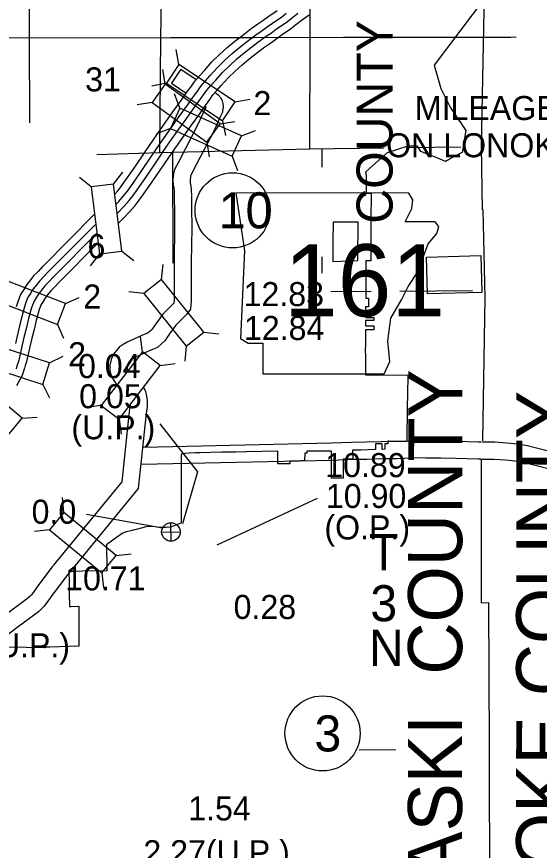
# Model space of a CAD drawing. Extents: x 1127717 to 1741049, y 2026793 to 2244711.
# Drawn here: x 1243581 to 1248173, y 2140586 to 2147909 of the extents above; entities that cross this region are included whole.
import ezdxf

# ---------------------------------------------------------------- set-up
doc = ezdxf.new("R2010")
doc.units = 0
for name, color, linetype in [('10', 7, 'Continuous'), ('15', 7, 'Continuous'), ('2', 7, 'Continuous'), ('20', 7, 'Continuous'), ('21', 7, 'Continuous'), ('25', 7, 'Continuous'), ('27', 7, 'Continuous'), ('30', 7, 'Continuous'), ('4', 7, 'Continuous'), ('5', 7, 'Continuous'), ('58', 7, 'Continuous'), ('6', 7, 'Continuous'), ('Level 30', 7, 'Continuous')]:
    doc.layers.add(name, color=color, linetype=linetype)

msp = doc.modelspace()

# ---------------------------------------------------------------- linework, layer by layer
at = {"layer": '10'}
for points in [[(1245024.4, 2147449.2), (1244939.9, 2147325.2), (1245069.5, 2147236.7)], [(1245024.4, 2147449.2), (1245158.6, 2147357.8)], [(1245324.8, 2147243.9), (1245333.9, 2147236.8), (1245350.9, 2147223.7), (1245374.5, 2147194.8), (1245385.9, 2147169.6), (1245391.2, 2147147.8), (1245394.7, 2147120.3), (1245391.6, 2147092.9), (1245390.1, 2147083.9), (1245387.8, 2147069.8), (1245378.9, 2147047.5), (1245363.6, 2147017.2), (1245338.1, 2146962.1), (1245311.8, 2146904.5), (1245132.7, 2146558.7)], [(1245234.6, 2147123.5), (1245241.4, 2147118.2), (1245242.4, 2147117.4), (1245242, 2147113.4), (1245241.5, 2147110.4), (1245241.1, 2147109.4), (1245227.6, 2147082.9), (1245200.8, 2147024.9), (1245175.4, 2146969.2), (1244998.8, 2146626.3)], [(1244998.8, 2146626.3), (1244974.7, 2146578.6), (1244968.4, 2146563.9), (1244964.3, 2146551.3), (1244960, 2146533.3), (1244954.2, 2146476.3), (1244953.8, 2146456.6), (1244954.9, 2146439.8), (1244956.7, 2146426.6), (1244960.5, 2146412.4), (1244962, 2146405), (1244964.1, 2146377.2), (1244965.9, 2146332.6)], [(1245132.7, 2146558.7), (1245110.7, 2146515.1), (1245108.9, 2146510.8), (1245108.7, 2146510.3), (1245108.2, 2146508.2), (1245104.1, 2146467), (1245103.9, 2146459.7), (1245104.1, 2146455.9), (1245106.5, 2146446.7), (1245110.8, 2146426.1), (1245113.9, 2146385.8), (1245115.7, 2146338.5)], [(1244965.9, 2146332.6), (1244966.5, 2146179), (1244968.4, 2146102.4), (1244968.6, 2146020.3), (1244967.6, 2145940.7), (1244965.7, 2145877.6), (1244964.7, 2145778.9), (1244963.9, 2145695.1), (1244964.4, 2145606.7), (1244964.2, 2145517.3), (1244964.1, 2145468), (1244964.3, 2145419.3), (1244962.4, 2145393.3), (1244961.7, 2145392.5), (1244866.1, 2145296.7)], [(1245115.9, 2146333.3), (1245116.5, 2146181.1), (1245118.4, 2146104.5), (1245118.6, 2146019.6), (1245117.6, 2145937.5), (1245115.7, 2145874.5), (1245114.7, 2145777.4), (1245113.9, 2145694.8), (1245114.4, 2145607), (1245114.2, 2145517), (1245114.1, 2145468), (1245114.3, 2145414.1), (1245108.8, 2145339.5), (1245076, 2145294.6), (1244980.1, 2145198.6)], [(1244265.7, 2146173.8), (1243809.8, 2145715.8)], [(1244276.4, 2146087.1), (1243858.5, 2145667.3)], [(1244286.2, 2146008.3), (1243902.8, 2145623.2)], [(1244296.9, 2145921.6), (1243951.5, 2145574.7)], [(1244866.1, 2145296.7), (1244802.1, 2145210.1), (1244769, 2145160.9), (1244755.9, 2145148.9), (1244736.7, 2145132.3), (1244715.7, 2145123.2), (1244680.2, 2145108.9), (1244550.1, 2145050.5), (1244515, 2145030.5), (1244482.4, 2145006.2), (1244456.6, 2144976.6), (1244429.3, 2144940.4), (1244411.4, 2144898.4), (1244400.1, 2144848.9), (1244400, 2144798.5), (1244411.7, 2144756.9), (1244428.4, 2144721), (1244452.7, 2144686.6), (1244459.6, 2144679.1)], [(1244980.1, 2145198.6), (1244924.7, 2145123.6), (1244883.4, 2145062.3), (1244855.7, 2145037), (1244817.5, 2145003.8), (1244773.4, 2144984.8), (1244739, 2144970.9), (1244618, 2144916.5), (1244597.2, 2144904.7), (1244584.9, 2144895.6), (1244573.1, 2144882), (1244560.1, 2144864.8), (1244554.7, 2144852), (1244550.1, 2144831.9), (1244550.1, 2144819.1), (1244552.9, 2144809), (1244557.3, 2144799.6)], [(1244693.8, 2144655.6), (1244697.7, 2144649.4), (1244712.4, 2144617.5), (1244722.2, 2144576.2), (1244725.9, 2144537.2), (1244726.9, 2144484.7), (1244721.9, 2144442.3), (1244716.4, 2144396.5), (1244649.2, 2143763.3), (1244016.9, 2142992.7)], [(1244576.5, 2144506.7), (1244576.8, 2144492.1), (1244573, 2144460.1), (1244567.3, 2144413.4), (1244504.7, 2143823.8), (1243900.9, 2143087.8)], [(1247664.5, 2144170.7), (1247637.9, 2144170.7), (1247443.6, 2144176.8), (1247311.4, 2144180.4), (1247180.9, 2144181.4), (1247141.5, 2144183.3), (1247047.7, 2144180.5), (1246920, 2144176.1), (1246784.7, 2144173.5), (1246653.7, 2144170.1), (1246521.6, 2144168.1), (1246345.9, 2144161.2), (1244694.8, 2144124.4)], [(1247672.2, 2144173), (1247781.7, 2144173.1), (1247888.2, 2144166.6), (1247950.3, 2144158.9), (1247973, 2144157.1), (1248019.2, 2144151.8), (1248065.5, 2144141.6), (1248438.7, 2144048.5)], [(1247663.1, 2144020.7), (1247635.4, 2144020.7), (1247439.2, 2144026.9), (1247308.7, 2144030.4), (1247176.7, 2144031.4), (1247140.1, 2144033.2), (1247052.5, 2144030.6), (1246924, 2144026.2), (1246788.1, 2144023.6), (1246656.9, 2144020.1), (1246525.7, 2144018.1), (1246350.5, 2144011.3), (1244673.1, 2143973.8)], [(1247671.4, 2144023), (1247777.1, 2144023.1), (1247874.4, 2144017.1), (1247935.2, 2144009.7), (1247958.5, 2144007.8), (1247994.3, 2144003.7), (1248031.1, 2143995.6), (1248402.3, 2143903)], [(1243898.9, 2143085.3), (1243769, 2142912), (1243734.4, 2142862.7), (1243709.9, 2142830.5), (1243698.6, 2142819.4), (1243674.7, 2142797.3), (1243491.4, 2142660.2), (1243211.8, 2142447.8), (1242963, 2142262.3), (1242790.6, 2142134.3), (1242584.6, 2141983.8), (1242522, 2141937.1), (1242493.2, 2141917.6), (1242476.6, 2141902.6), (1242450.7, 2141877.1), (1242424.4, 2141844.8), (1242306.6, 2141708.8), (1242245, 2141634.7), (1242230.2, 2141613.9)], [(1244018.9, 2142995.3), (1243890.4, 2142823.9), (1243855.5, 2142774.2), (1243822.8, 2142731.1), (1243802.2, 2142710.9), (1243771, 2142681.9), (1243581.7, 2142540.4), (1243302, 2142328), (1243052.6, 2142142), (1242879.6, 2142013.5), (1242673.7, 2141863.1), (1242608.9, 2141814.8), (1242585.9, 2141799.2), (1242579.4, 2141793.3), (1242561.8, 2141776), (1242539.3, 2141748.4), (1242421, 2141611.8), (1242363.9, 2141543.1), (1242339.2, 2141508.4), (1242308.1, 2141461.2), (1242275.8, 2141417), (1242253.4, 2141381.2), (1242227.4, 2141356.2)]]:
    msp.add_lwpolyline(points, dxfattribs=at)
at = {"layer": '15'}
for points in [[(1244443.3, 2146351), (1244468.1, 2146379), (1244498.4, 2146416.7), (1244526.1, 2146455.9), (1244613, 2146579.5), (1244708.9, 2146720.8), (1244784.4, 2146832.9), (1244890.6, 2146984.9), (1244953.7, 2147073.3), (1245025.7, 2147172.7), (1245077.2, 2147247), (1245115.6, 2147297.8), (1245146.2, 2147343.6), (1245189.3, 2147392.7), (1245230.1, 2147437.6), (1245295.8, 2147511.1), (1245358.8, 2147573.9), (1245430.3, 2147638.5), (1245498.5, 2147693.9), (1245566.5, 2147746.9), (1245642, 2147804.9), (1245699.3, 2147844.8), (1245742.5, 2147874.5), (1245788.7, 2147908.7), (1245869.4, 2147964.4)], [(1244454.4, 2146261), (1244477.5, 2146285.9), (1244520.7, 2146334.7), (1244553.3, 2146375.3), (1244582.3, 2146416.3), (1244669.5, 2146540.4), (1244765.9, 2146682.3), (1244841.1, 2146794), (1244946.7, 2146945.3), (1245009.5, 2147033.2), (1245081.8, 2147133), (1245132.9, 2147206.6), (1245171.7, 2147257.9), (1245200.9, 2147301.7), (1245240.5, 2147346.9), (1245281.2, 2147391.6), (1245345.7, 2147463.8), (1245406.2, 2147524), (1245475, 2147586.3), (1245541.3, 2147640.2), (1245608.6, 2147692.6), (1245682.6, 2147749.4), (1245738.4, 2147788.2), (1245782.4, 2147818.6), (1245828.7, 2147852.7), (1245910.1, 2147909), (1245949.8, 2147939.9)], [(1244464.4, 2146180), (1244523.8, 2146243.9), (1244568.5, 2146294.4), (1244603.2, 2146337.6), (1244633.4, 2146380.2), (1244721, 2146504.9), (1244817.6, 2146647.3), (1244892.7, 2146758.7), (1244997.8, 2146909.2), (1245060.3, 2146996.7), (1245132.8, 2147096.8), (1245183.6, 2147170), (1245222.6, 2147221.7), (1245250.6, 2147263.6), (1245287.2, 2147305.3), (1245327.6, 2147349.7), (1245391.1, 2147420.8), (1245449.2, 2147478.7), (1245515.7, 2147538.8), (1245580.2, 2147591.3), (1245646.8, 2147643.1), (1245719.4, 2147698.9), (1245774, 2147736.8), (1245818.7, 2147767.7), (1245865, 2147801.8), (1245947.2, 2147858.6), (1245988.2, 2147890.6), (1246051.3, 2147939.4)], [(1244474.8, 2146096.4), (1244519.2, 2146137.9), (1244574.8, 2146197.7), (1244621.1, 2146250.1), (1244658.1, 2146296.2), (1244689.6, 2146340.6), (1244777.5, 2146465.8), (1244874.6, 2146608.8), (1244949.4, 2146719.8), (1245053.9, 2146869.5), (1245116.1, 2146956.5), (1245188.9, 2147057), (1245239.3, 2147129.6), (1245278.7, 2147181.9), (1245305.3, 2147221.6), (1245338.5, 2147259.5), (1245378.7, 2147303.7), (1245441.1, 2147373.6), (1245496.5, 2147428.8), (1245560.5, 2147486.6), (1245623.1, 2147537.5), (1245688.9, 2147588.8), (1245760, 2147643.4), (1245813.1, 2147680.3), (1245858.6, 2147711.7), (1245904.9, 2147745.9), (1245987.9, 2147803.1), (1246030.4, 2147836.3), (1246092.7, 2147884.5), (1246149.8, 2147926.6)], [(1243807.7, 2145713.6), (1243768.5, 2145671.8), (1243728.3, 2145631.8), (1243705.3, 2145600.8), (1243670.5, 2145557.2), (1243642.6, 2145513.4), (1243615.1, 2145468.4), (1243590, 2145403), (1243576.8, 2145359.2)], [(1243857.9, 2145666.6), (1243817.8, 2145623.9), (1243780.4, 2145586.7), (1243759.8, 2145558.9), (1243726.6, 2145517.2), (1243700.9, 2145477), (1243677.1, 2145437.9), (1243655.1, 2145380.7), (1243643, 2145340.5), (1243625.1, 2145272.6), (1243606.9, 2145193.2), (1243586.6, 2145116.6), (1243569.4, 2145039.5)], [(1243903.5, 2145623.8), (1243862.7, 2145580.3), (1243827.8, 2145545.6), (1243809.3, 2145520.8), (1243777.5, 2145480.8), (1243753.9, 2145443.9), (1243733.4, 2145410.2), (1243714.2, 2145360.5), (1243703.1, 2145323.5), (1243685.8, 2145257.7), (1243667.6, 2145178.2), (1243647.4, 2145101.7), (1243630.2, 2145025), (1243613.5, 2144959.3), (1243598.3, 2144887.6), (1243590.9, 2144866.7), (1243583, 2144842.4), (1243574.8, 2144816.3)], [(1243953.6, 2145576.8), (1243912, 2145532.4), (1243879.9, 2145500.5), (1243863.8, 2145478.9), (1243833.5, 2145440.8), (1243812.3, 2145407.6), (1243795.3, 2145379.7), (1243779.3, 2145338.2), (1243769.3, 2145304.9), (1243752.6, 2145241.3), (1243734.4, 2145161.7), (1243714.2, 2145085.4), (1243697, 2145009), (1243680.5, 2144943.7), (1243664.6, 2144868.9), (1243656, 2144844.7), (1243648.5, 2144821.5), (1243640.2, 2144794.9), (1243625, 2144750.8), (1243600.4, 2144703.6), (1243580.4, 2144667.7)]]:
    msp.add_lwpolyline(points, dxfattribs=at)
at = {"layer": '2'}
for points in [[(1247597.6, 2151689.9), (1247594.9, 2150725.5), (1247690.9, 2150725.1), (1247700.5, 2149465), (1247688.4, 2148116.6), (1247661.8, 2146767.3), (1247669.5, 2146213.4)], [(1247677.3, 2146215.7), (1247694.3, 2145442.6), (1247672.5, 2144184.2)], [(1247663.1, 2144020.7), (1247662.8, 2142760.5), (1247726.6, 2142761.9), (1247731.3, 2141494.2), (1247734.4, 2140166.2), (1247725.8, 2138824.4), (1247726.7, 2138603.6)]]:
    msp.add_lwpolyline(points, dxfattribs=at)
at = {"layer": '20'}
for p, q in [((1245006.4, 2147489.9), (1244980.7, 2147619.4)), ((1244886.3, 2147316.1), (1244865.5, 2147446.4)), ((1244896.4, 2147325.3), (1244766.9, 2147299.6)), ((1245013.3, 2147106.5), (1244966.5, 2147230)), ((1245500.2, 2147159.9), (1245629.7, 2147185.6)), ((1244770.2, 2147155.7), (1244639.8, 2147134.9)), ((1245013.3, 2147106.5), (1244932.1, 2146926)), ((1245555, 2146862.8), (1245013.3, 2147106.5)), ((1245367.4, 2146967.7), (1245497.7, 2146988.5)), ((1245390.2, 2146995.2), (1245415.9, 2146865.8)), ((1244932.1, 2146926), (1244808.7, 2146879.1)), ((1244932.1, 2146926), (1245473.8, 2146682.3)), ((1245555, 2146862.8), (1245678.4, 2146909.6)), ((1245473.8, 2146682.3), (1245555, 2146862.8)), ((1245251.2, 2146807.3), (1245272.1, 2146677)), ((1245473.8, 2146682.3), (1245520.6, 2146558.8)), ((1244432.5, 2146438.6), (1244513.7, 2146542.7)), ((1244236, 2146414.3), (1244131.9, 2146495.5)), ((1244308.8, 2145824.8), (1244227.6, 2145720.7)), ((1244505.3, 2145849.1), (1244609.4, 2145767.9)), ((1244852.7, 2145600.8), (1244866.8, 2145732)), ((1244698.5, 2145476.5), (1244567.2, 2145490.7)), ((1244010.3, 2145389.7), (1244130.9, 2145443.3)), ((1243939.1, 2145205), (1243992.7, 2145084.3)), ((1245225.3, 2145138.2), (1245356.6, 2145124.1)), ((1244685.2, 2144965.8), (1244667.7, 2145096.6)), ((1245071.1, 2145014), (1245057, 2144882.7)), ((1243870.5, 2144867), (1243988.1, 2144926.8)), ((1244842.5, 2144845.6), (1244973.4, 2144863.1)), ((1243809.2, 2144678.7), (1243869, 2144561)), ((1244324.5, 2144493.8), (1244193.7, 2144476.3)), ((1243629.9, 2144380.9), (1243761.5, 2144392)), ((1244481.9, 2144373.6), (1244499.3, 2144242.8)), ((1243995.5, 2143553.1), (1243982.5, 2143684.5)), ((1243869.9, 2143400), (1243738.5, 2143387.1)), ((1244454.7, 2143176.3), (1244586.1, 2143189.3)), ((1244329.1, 2143023.3), (1244342.1, 2142891.9))]:
    msp.add_line(p, q, dxfattribs=at)
for points in [[(1245500.2, 2147159.9), (1245006.4, 2147489.9), (1244896.4, 2147325.3), (1245390.2, 2146995.2)], [(1245367.4, 2146967.7), (1244886.3, 2147316.1), (1244770.2, 2147155.7), (1245251.2, 2146807.3)], [(1244505.3, 2145849.1), (1244432.5, 2146438.6), (1244236, 2146414.3), (1244308.8, 2145824.8)], [(1243384.8, 2145418.4), (1243939.1, 2145205), (1244010.3, 2145389.7), (1243456, 2145603.2)], [(1244698.5, 2145476.5), (1245071.1, 2145014), (1245225.3, 2145138.2), (1244852.7, 2145600.8)], [(1243244.4, 2144862.7), (1243809.2, 2144678.7), (1243870.5, 2144867), (1243305.7, 2145051)], [(1244481.9, 2144373.6), (1244842.5, 2144845.6), (1244685.2, 2144965.8), (1244324.5, 2144493.8)], [(1243629.9, 2144380.9), (1243175.9, 2144763.9), (1243048.3, 2144612.5), (1243502.3, 2144229.5)], [(1244454.7, 2143176.3), (1243995.5, 2143553.1), (1243869.9, 2143400), (1244329.1, 2143023.3)]]:
    msp.add_lwpolyline(points, close=True, dxfattribs=at)
at = {"layer": '21'}
msp.add_lwpolyline([(1245505.9, 2146360.6), (1245582, 2145853.1), (1245548.2, 2145083.3), (1245615.9, 2145041), (1245742.7, 2145041), (1245742.7, 2144770.4), (1246808.6, 2144770.4), (1246859.3, 2144880.3), (1246842.4, 2145058), (1246867.8, 2145261), (1246960.8, 2145421.7), (1247020, 2145540.1), (1247104.6, 2145667), (1247155.4, 2145802.3), (1247197.7, 2145912.3), (1247273.8, 2146005.4), (1247290.7, 2146064.6), (1247256.9, 2146106.9), (1246994.7, 2146106.9), (1247053.9, 2146225.3), (1247062.3, 2146301.4), (1247027.3, 2146359.9)], close=True, dxfattribs=at)
at = {"layer": '25'}
for p, q in [((1244937.9, 2143301.3), (1244934.1, 2143464.1)), ((1244854.7, 2143380.8), (1245017.4, 2143384.6))]:
    msp.add_line(p, q, dxfattribs=at)
msp.add_lwpolyline([(1244861, 2143415.3), (1244194.1, 2143536.6)], dxfattribs=at)
msp.add_circle((1244936, 2143382.7), 81.4, dxfattribs=at)
at = {"layer": '27'}
for centre in [(1245478.1, 2146207.8), (1246268.2, 2141612.9)]:
    msp.add_circle(centre, 330, dxfattribs=at)
at = {"layer": '30'}
for q in [(1247968.3, 2147730.6), (1247923.9, 2147730.5)]:
    msp.add_line((1238326.3, 2147717.7), q, dxfattribs=at)
at = {"layer": '4'}
for points in [[(1243681.3, 2151440.5), (1243680.1, 2150655.8), (1243685.7, 2149325.8), (1243689, 2148006.4), (1243690.2, 2147724.8)], [(1243690.2, 2147724.8), (1243693.6, 2146977)], [(1244284.9, 2146699), (1244838.3, 2146714.5), (1246156.7, 2146746.9), (1246809.3, 2146756.1)], [(1247012.8, 2146758.9), (1247482.9, 2146765.5)]]:
    msp.add_lwpolyline(points, dxfattribs=at)
at = {"layer": '5'}
for points in [[(1244848.3, 2147726.4), (1244851.9, 2148062), (1244842.5, 2149408.9), (1244847.7, 2150774.7), (1244852.7, 2151676.2)], [(1246159.2, 2147728.1), (1246160.6, 2148082.1), (1246169.1, 2149411.4), (1246171.1, 2150787.1), (1246168.3, 2151684.2)], [(1244837.3, 2146716), (1244848.3, 2147726.4)], [(1246155.2, 2146747.9), (1246159.2, 2147728.1)], [(1246263.7, 2146586.1), (1246263.7, 2146749.3)], [(1244956.5, 2145744.6), (1244954.2, 2146717.6)], [(1246263.6, 2145656.7), (1246263.6, 2145798.6)], [(1246340.1, 2145494.1), (1246694.7, 2145496.9)], [(1246948.3, 2145498.9), (1247586, 2145503.9)], [(1246590.3, 2141467.9), (1246913.2, 2141471.3)]]:
    msp.add_lwpolyline(points, dxfattribs=at)
at = {"layer": '58'}
msp.add_line((1245343.3, 2143270.1), (1246222.9, 2143678.5), dxfattribs=at)
msp.add_lwpolyline([(1244839.9, 2144333.4), (1245170.6, 2143911), (1245038.4, 2143453)], dxfattribs=at)
at = {"layer": '6'}
for points in [[(1247700.8, 2148083.3), (1247248.4, 2147482.3), (1247307.4, 2147279.6), (1247389.1, 2147114.3), (1247410.8, 2147082.4), (1247446.3, 2147030.1), (1247480.1, 2146980.3), (1247481.9, 2146977.6), (1247492.2, 2146962.3), (1247527.4, 2146910.4), (1247510.2, 2146807), (1247504, 2146769.6), (1247494.3, 2146716), (1247437.6, 2146685.5), (1247363, 2146645.4), (1247349, 2146637.8), (1247279.9, 2146665.6), (1247132.8, 2146724.6), (1247103.8, 2146771.9), (1247016.9, 2146772.3), (1246835.1, 2146711.6), (1246684.5, 2146577.9), (1246646.4, 2146544), (1246648.3, 2146535.8), (1246648.3, 2146535.8), (1246649.6, 2146527.5), (1246649.6, 2146527.5), (1246650.4, 2146519.2), (1246650.4, 2146519.2), (1246650.7, 2146510.8), (1246650.4, 2146404.6), (1246650.4, 2146403.2), (1246650.4, 2146401.9), (1246650.4, 2146401.6), (1246650.3, 2146360), (1246694.7, 2146358.5), (1246693.8, 2146112.5), (1246693.8, 2146111.2), (1246693.8, 2146109.9), (1246693.8, 2146103.7), (1246692.6, 2145765.5), (1246648.7, 2145765.6), (1246647.9, 2145437.7), (1246671.4, 2145437.8), (1246671.4, 2145434.1), (1246671.5, 2145431.3), (1246671.5, 2145428.5), (1246671.6, 2145424.5), (1246671.5, 2145394.5), (1246671.5, 2145391), (1246671.4, 2145361.4), (1246646.7, 2145361.4), (1246646.8, 2145342.4), (1246646.8, 2145321.8), (1246646.8, 2145308.6), (1246647, 2145295.5), (1246647.1, 2145281.6), (1246647.1, 2145266.3), (1246655.1, 2145266.4), (1246656.3, 2145266.4), (1246668.1, 2145266.4), (1246673.7, 2145266.4), (1246697.3, 2145266.4), (1246697.7, 2145266.4), (1246699.4, 2145266.4), (1246719.2, 2145266.3), (1246719.1, 2145241.4), (1246715.2, 2145241.4), (1246647, 2145241.4), (1246647, 2145222), (1246646.9, 2145210.8), (1246646.9, 2145210.7), (1246646.9, 2145201.1), (1246646.8, 2145193.6), (1246651.1, 2145193.6), (1246651.2, 2145193.6), (1246714.3, 2145193.6), (1246719, 2145193.7), (1246719, 2145158.5), (1246646.7, 2145158.7), (1246646.6, 2145124.9), (1246646.5, 2145102.5), (1246646.3, 2145096.1), (1246646.3, 2145094), (1246646.2, 2145091.7), (1246644.7, 2145026.4), (1246643.6, 2144980.8), (1246646, 2144928.7), (1246645.6, 2144761.6), (1247016.2, 2144760.9), (1247013.6, 2144588.8), (1247012, 2144479.5), (1247007.4, 2144177.9), (1246856.2, 2144178.2), (1246851.7, 2144178.8)], [(1246851.7, 2144178.8), (1246848.7, 2144179.2), (1246846, 2144179.6), (1246842.6, 2144180), (1246842.1, 2144156.3), (1246815.9, 2144156.4), (1246816.8, 2144108.7), (1246792.5, 2144107.8), (1246791.6, 2144156.4), (1246783.7, 2144156.4), (1246773.6, 2144156.5), (1246732.3, 2144156.6), (1246732.2, 2144105.9), (1246604.2, 2144102.3), (1246580.6, 2144101.6), (1246574.7, 2144101.5), (1246570.2, 2144101.3), (1246549.6, 2144100.8), (1246539.5, 2144100.5), (1246531.4, 2144100.2), (1246531.7, 2144095.1), (1246531.8, 2144092.9), (1246531.9, 2144090.6), (1246535, 2144023.9), (1246449.5, 2144022.9), (1246450.5, 2143858.7), (1246450.5, 2143855.4), (1246355.6, 2143854.6), (1246352.5, 2143854.5), (1246349.8, 2143854.5), (1246346.5, 2143854.5), (1246347.1, 2144083.6), (1246347.1, 2144086.9), (1246347.1, 2144089.2), (1246347.1, 2144092), (1246268.1, 2144092.3), (1246265.2, 2144092.4), (1246262.8, 2144092.4), (1246137.2, 2144092.9), (1246129, 2144092.9), (1246129, 2144092.7), (1246129, 2144088.9), (1246129, 2144086.6), (1246129, 2144084.2), (1246129.1, 2144075.2), (1246111.3, 2144074.8), (1246110.5, 2144006.3), (1246080.6, 2144006.1), (1246065.7, 2144005.9), (1245980.7, 2144005.1), (1245980.6, 2143982.2), (1245876, 2143981.3), (1245876.7, 2144081.7), (1245876.7, 2144083.7), (1245876.7, 2144086.1), (1245876.8, 2144091.8), (1245601.9, 2144086.7), (1245598.8, 2144086.6), (1245595.7, 2144086.6), (1245504.1, 2144084.9), (1245500.7, 2144084.8), (1245498.5, 2144084.8), (1245497.1, 2144084.7), (1245495.1, 2144084.7), (1245491.6, 2144084.6), (1245384.7, 2144082.6), (1245192.7, 2144079.1), (1245190.5, 2144079), (1245164.9, 2144078.2), (1245156.5, 2144077.9), (1245153.6, 2144077.8), (1245151, 2144077.8), (1245095.1, 2144075.9), (1245059.3, 2144071.9), (1245038.6, 2144069.5), (1245034.7, 2144069.1), (1245031.2, 2144068.7), (1245029.8, 2144068.5), (1245027.6, 2144064), (1245027.5, 2144063.7), (1245025.9, 2144060.4), (1245025.1, 2144058.8), (1245025.1, 2144057.6), (1245024.7, 2143484.3), (1245024.7, 2143462.1), (1245022.2, 2143461.1), (1244965, 2143437.8), (1244933.4, 2143426.1), (1244932.2, 2143426), (1244894.5, 2143421.7), (1244866.8, 2143421.8), (1244818.7, 2143425.3), (1244780.5, 2143429.1), (1244757.7, 2143431.3), (1244739.3, 2143430.7), (1244702.4, 2143423.5), (1244698.9, 2143422.6), (1244618.2, 2143401.8), (1244615.9, 2143401.2), (1244602.2, 2143397.5)], [(1244602.2, 2143397.5), (1244594.6, 2143395.8), (1244556.9, 2143386.1), (1244556.3, 2143385.9), (1244545.5, 2143382.5), (1244536.2, 2143380.7), (1244518.9, 2143376.1), (1244507.5, 2143368.1), (1244459.2, 2143334.1), (1244370.5, 2143269.3), (1244373.4, 2143061.7), (1244373.7, 2143039.8), (1244159.1, 2143036.9), (1244099.8, 2143036.1), (1244039.5, 2143035.3), (1244040.8, 2142941.9), (1244040.9, 2142937.6), (1244040.9, 2142932.9), (1244041.3, 2142901.3), (1244041.4, 2142897), (1244042.1, 2142844.3), (1244042.1, 2142842.1), (1244043.7, 2142728.6), (1244058.3, 2142729.1), (1244127.2, 2142731.2), (1244127.1, 2142720), (1244127.1, 2142718.7), (1244127.1, 2142717.4), (1244126.6, 2142627.8), (1244126.4, 2142603.9), (1244125.8, 2142504), (1244127.5, 2142492.2), (1244127.8, 2142489.4), (1244128.2, 2142486.6), (1244128.2, 2142486.5), (1244128.2, 2142471.4), (1244128.2, 2142471.1), (1244128.1, 2142459.4), (1244128.1, 2142459.2), (1244127.7, 2142380.4), (1243872.5, 2142371.8), (1243866.9, 2142371.6), (1243831.8, 2142370.5), (1243831.4, 2142365.8), (1243829.4, 2142365.8), (1243828, 2142365.8), (1243826.4, 2142365.9), (1243503, 2142369.1)]]:
    msp.add_lwpolyline(points, dxfattribs=at)
for points in [[(1246358.9, 2145758.6), (1246360, 2145758.6), (1246497.9, 2145763.2), (1246578.9, 2145765.8), (1246579.2, 2145795.9), (1246582.1, 2146087.9), (1246582.2, 2146104), (1246360.1, 2146104.6), (1246359.5, 2145937.5), (1246359.5, 2145919.1)], [(1247190.6, 2145473.1), (1247180.9, 2145796.2), (1247658.6, 2145810.5), (1247668.3, 2145487.4)]]:
    msp.add_lwpolyline(points, close=True, dxfattribs=at)

# ---------------------------------------------------------------- texts
at = {"layer": '20'}
for p in [(1245660.6, 2147044), (1244165.8, 2145345.1), (1244033.2, 2144838.3)]:
    msp.add_text('2', height=211.2, dxfattribs=at).set_placement(p)
at = {"layer": '21'}
msp.add_text('161', height=633.6, dxfattribs=at).set_placement((1245930.3, 2145276.7))
at = {"layer": '25'}
msp.add_text('0.0', height=211.2, dxfattribs=at).set_placement((1243711.8, 2143454.9))
at = {"layer": '27'}
for s, p in [('10', (1245356, 2146049.4)), ('3', (1246197.3, 2141454.5))]:
    msp.add_text(s, height=316.8, dxfattribs=at).set_placement(p)
at = {"layer": '30'}
msp.add_text('COUNTY', height=316.8, rotation=90, dxfattribs=at).set_placement((1246883.5, 2146090.6))
for s, height, p in [('MILEAGE CARRIED', 211.2, (1247078.9, 2147001.1)), ('ON LONOKE CO. LOG', 211.2, (1246826.7, 2146674.2)), ('T', 316.8, (1246676.9, 2143046.7)), ('3', 316.8, (1246688.4, 2142598.2)), ('N', 316.8, (1246675.5, 2142206.3))]:
    msp.add_text(s, height=height, dxfattribs=at).set_placement(p)
at = {"layer": '5'}
for s, p in [('31', (1244182.2, 2147252.8)), ('6', (1244202.8, 2145786.9))]:
    msp.add_text(s, height=211.2, dxfattribs=at).set_placement(p)
at = {"layer": '58'}
for s, p in [('12.83', (1245574.3, 2145366.4)), ('12.84', (1245577.5, 2145068.9)), ('0.04', (1244119.4, 2144734.2)), ('0.05', (1244129.6, 2144469.5)), ('(U.P.)', (1244061.1, 2144196.7)), ('10.89', (1246291.6, 2143864)), ('10.90', (1246297.6, 2143593.2)), ('(O.P.)', (1246284.4, 2143316.9)), ('10.71', (1244006.5, 2142868.9)), ('0.28', (1245486.7, 2142618.4)), ('9.81(U.P.)', (1242762.5, 2142281.5)), ('1.54', (1245087.9, 2140848.6)), ('2.27(U.P.)', (1244693.8, 2140463.6))]:
    msp.add_text(s, height=211.2, dxfattribs=at).set_placement(p)
at = {"layer": 'Level 30'}
for s, p in [('PULASKI  COUNTY', (1247492.9, 2139091.4)), ('LONOKE COUNTY', (1248443.3, 2139114.5))]:
    msp.add_text(s, height=475.199, rotation=89.9667, dxfattribs=at).set_placement(p)

doc.saveas('drawing.dxf')
